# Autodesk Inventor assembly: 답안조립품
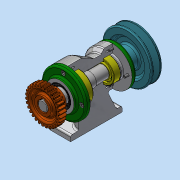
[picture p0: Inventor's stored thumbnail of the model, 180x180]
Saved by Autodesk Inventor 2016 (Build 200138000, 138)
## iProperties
Created: 2019-01
Part Number: 답안조립품
Material: 일반
Document SubType Name: Assembly
Designer: Administrator
Author: Administrator
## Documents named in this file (15)
- C:\Users\Administrator\Desktop\490107V1036\답안조립품.iam
- C:\Users\Administrator\Desktop\490107V1036\본체.ipt
- C:\Users\Administrator\Desktop\490107V1036\베어링 6205.ipt
- C:\Users\Administrator\Desktop\490107V1036\베어링 6203.ipt
- C:\Users\Administrator\Desktop\490107V1036\축.ipt
- C:\Users\Administrator\Desktop\490107V1036\뒤커버.ipt
- C:\Users\Administrator\Desktop\490107V1036\오일 실 17 30 8.ipt
- C:\Users\Administrator\Desktop\490107V1036\볼트 M4.ipt
- C:\Users\Administrator\Desktop\490107V1036\키 5 x 5 x 20.ipt
- C:\Users\Administrator\Desktop\490107V1036\멈춤나사 M3.ipt
- C:\Users\Administrator\Desktop\490107V1036\V-벨트풀리.ipt
- C:\Users\Administrator\Desktop\490107V1036\앞커버.ipt
- C:\Users\Administrator\Desktop\490107V1036\키 6 x 6 x 18.ipt
- C:\Users\Administrator\Desktop\490107V1036\스퍼기어.ipt
- C:\Users\Administrator\Desktop\490107V1036\오일 실 25 38 8.ipt
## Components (1 placed, 1 different names)
1. V-벨트풀리:1
